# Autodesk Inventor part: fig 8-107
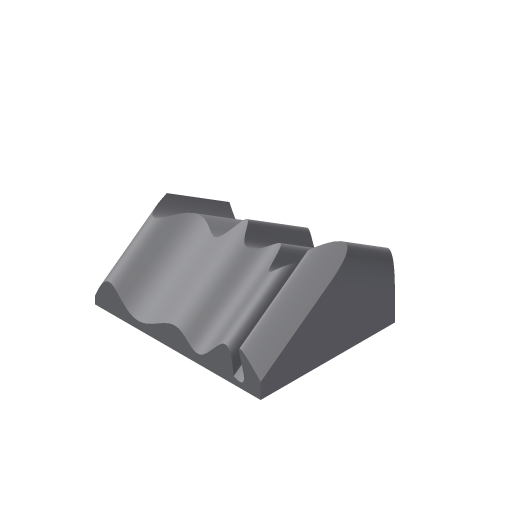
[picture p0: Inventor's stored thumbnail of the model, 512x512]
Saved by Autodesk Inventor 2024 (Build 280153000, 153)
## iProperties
Shininess: 64.0
Length Units: 11269
Angle Units: 11279
Time Units: 11290
Mass Units: 11283
Length Display Precision: 3
Angle Display Precision: 2
Compacted: True
Part Number: fig 8-107
Document SubType Name: Modeling
Created: 2002-12
Designer: deepak
Density: 1 g/cm^3
Material: Generic
Appearance: Default
Density: 0.0
Volumn: 0.0
Area: 0.0
PropertySet Name: Model Information
Control State: 0
Master: False
Checked Out: False
Author: deepak
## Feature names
1. Extrusion1
## Parameters: d1 = 0, d2 = 0, d3 = 0, d4 = 0, d5 = 0
